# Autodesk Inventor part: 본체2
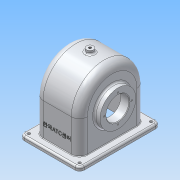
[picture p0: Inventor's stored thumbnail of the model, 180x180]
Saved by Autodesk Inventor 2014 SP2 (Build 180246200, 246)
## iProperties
Created: 2016-01
Part Number: 본체2
Material: 알루미늄 6061
Document SubType Name: Modeling
Designer: User
Mass: 842.835 g
Surface Area: 990.698 cm^2
Volume: 311.009 cm^3
Density: 2.71 g/cm^3
Appearance: 알루미늄 - 평지
Author: User
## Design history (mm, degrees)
sketch "스케치1"
  geometry: L1 (-57, 0)-(57, 0); L2 (57, 0)-(57, -64); L3 (57, -64)-(-57, -64); L4 (-57, -64)-(-57, 0); C1 r 57 at (0, 0); 2 further points
  constraints: 8 end point, 2 coincident, 2 parallel, 1 centre point, 1 horizontal, 1 midpoint, 1 perpendicular
  dimensions: "d0" = 114 diameter of C1; "d1" = 114 distance of L2.end L3.end; "d2" = 64 distance of L1.end L2.end
extrude "돌출1" new body sketch "스케치1" stored distance "d3" = 77; taper "d4" = 0 deg
feature "쉘1" dims "d7" = 6
sketch "스케치3"
  geometry: L1 (114, 0)-(114, -77) reference; L2 (0, 0)-(114, 0) reference; L3 (0, 0)-(0, -77) reference; L4 (114, -77)-(0, -77) reference; L5 (-13, 13.5)-(127, 13.5); L6 (127, 13.5)-(127, -90.5); L7 (127, -90.5)-(-13, -90.5); L8 (-13, -90.5)-(-13, 13.5); 3 further points
  constraints: 8 end point, 2 midpoint, 2 parallel, 1 horizontal, 1 horizontal alignment, 1 perpendicular, 1 vertical alignment
  dimensions: "d8" = 140 distance of L5.start L5.end; "d9" = 104 distance of L5.end L6.end
extrude "돌출2" join sketch "스케치3" distance "d10" = 7; taper "d11" = 0 deg
fillet "모깎기1" dims "d12" = 14
node "작업 평면1"
sketch "스케치6"
  geometry: C1 r 6 at (0, 0); 1 further point
  constraints: 1 centre point, 1 coincident
  dimensions: "d36" = 12 diameter of C1
extrude "돌출4" join sketch "스케치6" stored distance "d37" = 10; taper "d38" = 0 deg
hole "구멍2" diameter "d41" = 4.459; stored, may be unused: countersink angle "d45" = 90 deg, drill point angle "d47" = 118 deg; dims "d39" = 10, "d40" = 10, "d42" = 6, "d43" = 4, "d44" = 2, "d46" = 63
fillet "모깎기4" dims "d77" = 8
sketch "스케치9"
  geometry: A1 r 8 centre (119, 82.5) between (127, 82.5) and (119, 90.5) reference; A2 r 8 centre (-5, 82.5) between (-5, 90.5) and (-13, 82.5) reference; A3 r 8 centre (-5, -5.5) between (-13, -5.5) and (-5, -13.5) reference; A4 r 8 centre (119, -5.5) between (119, -13.5) and (127, -5.5) reference; 1 further point
hole "구멍5" sketch "스케치9" at (119, 82.5), (-5, 82.5), (119, -5.5), (-5, -5.5) diameter "d78" = 5; stored, may be unused: countersink angle "d82" = 90 deg, drill point angle "d84" = 118 deg; dims "d79" = 7, "d80" = 4, "d81" = 2, "d83" = 9
fillet "모깎기5" dims "d85" = 3
sketch "스케치10"
  geometry: L1 (49, 0)-(49, -57) reference; L2 (0, 0)-(49, 0) reference; L3 (0, -57)-(0, 0) reference; L4 (-1.387, -30.398)-(50.387, -30.398); L5 (50.387, -30.398)-(50.387, -37.602); L6 (50.387, -37.602)-(-1.387, -37.602); L7 (-1.387, -37.602)-(-1.387, -30.398); L8 (0, -34)-(49, -34); L9 (-19.5, -64)-(68.5, -64) reference; L10 (24.5, 0)-(24.5, -54); L11 (-14, 0)-(-14, -57) reference; L12 (68.5, -57)-(-19.5, -57) reference; 4 further points
  constraints: 4 end point, 4 midpoint, 2 point on line, 1 horizontal alignment, 1 perpendicular, 1 vertical alignment, 2 other
  dimensions: "d86" = 30 distance between parallel lines of L9 L8; "d87" = 38.5 distance between parallel lines of L11 L10
feature "엠보싱1" sketch "스케치10" dims "d8" = 140, "d9" = 104, "d88" = 0.5, "d89" = 0
sketch "스케치11"
  geometry: L1 (-51, -64)-(-51, 0) reference; L2 (51, -64)-(-51, -64) reference; L3 (51, 0)-(51, -64) reference; C1 r 20 at (0, -4) reference; A1 r 51 centre (0, 0) between (51, 0) and (-51, 0) reference
extrude "돌출5" cut sketch "스케치11" distance "d90" = 1; taper "d91" = 0 deg
sketch "스케치12"
  geometry: L1 (-51, -64)-(-51, 0) reference; L2 (51, -64)-(-51, -64) reference; L3 (51, 0)-(51, -64) reference; C1 r 38.908 at (0, -4) reference; A1 r 51 centre (0, 0) between (51, 0) and (-51, 0) reference
extrude "돌출6" cut sketch "스케치12" distance "d92" = 1; taper "d93" = 0 deg
sketch "스케치13"
  geometry: L1 (-4, 43.197)-(-4, -48.942); L2 (-64, -33.5)-(-64, 33.5) reference; L3 (16, 35.5)-(30.899, 35.5); L4 (24, 35.5)-(24, 19.5); L5 (24, 19.5)-(16, 19.5); L6 (16, 19.5)-(16, 35.5); L7 (0, 38.5)-(43, 38.5) reference; L8 (24, 19.5)-(39.943, 38.5); L9 (30.899, 35.5)-(33.416, 38.5); L10 (-4, 33.5)-(16, 33.5); L11 (-4, 38.5)-(33.416, 38.5); L12 (-4, 38.5)-(-4, 33.5); 1 further point
  constraints: 20 end point, 6 point on line, 3 parallel, 2 perpendicular, 1 collinear, 1 horizontal, 1 vertical
  dimensions: "d95" = 60 distance between parallel lines of L1 L2; "d96" = 20 distance between parallel lines of L1 L6; "d99" = 50 deg angle of L8 L5; "d100" = 5 distance between parallel lines of L8 L9; "d102" = 5 distance between parallel lines of L10 L11; "d103" = 56 diameter of L4 L1; "d104" = 19 distance between parallel lines of L11 L5; "d105" = 3 distance between parallel lines of L11 L3
revolve "회전3" stored, may be unused: angle "d106" = 90 deg
revolve "회전4" stored, may be unused: angle "d107" = 90 deg
sketch "스케치14"
  geometry: C1 r 20 at (0, -4) reference; C2 r 31 at (0, -4)
  constraints: 1 centre point, 1 coincident
  dimensions: "d108" = 62 diameter of C2
extrude "돌출7" join sketch "스케치14" distance "d109" = 10; taper "d110" = 0 deg
hole "구멍6" diameter "d113" = 40; stored, may be unused: countersink angle "d117" = 90 deg, drill point angle "d119" = 118 deg; dims "d111" = 10, "d112" = 10, "d114" = 6, "d115" = 4, "d116" = 2, "d118" = 8
chamfer "모따기3" distance "d120" = 1; stored, may be unused: second distance "d121" = 2, angle "d122" = 45 deg
fillet "모깎기6" dims "d123" = 3
sketch "스케치15"
  geometry: C1 r 31 at (0, 0) reference; 2 further points
  constraints: 1 vertical alignment
  dimensions: "d124" = 24 distance of C1.centre point (0, 24)
hole "구멍7" sketch "스케치15" at (0, 24) diameter "d125" = 2.459; stored, may be unused: countersink angle "d129" = 90 deg, drill point angle "d131" = 118 deg; dims "d126" = 6, "d127" = 4, "d128" = 2, "d130" = 8
sketch "스케치16"
  geometry: C1 r 21 at (0, 0) reference; 2 further points
  constraints: 1 vertical alignment
  dimensions: "d135" = 28 distance of C1.centre point (0, 28)
hole "구멍8" sketch "스케치16" at (0, 28) diameter "d136" = 2.459; stored, may be unused: countersink angle "d140" = 90 deg, drill point angle "d142" = 118 deg; dims "d137" = 7, "d138" = 4, "d139" = 2, "d141" = 9
fillet "모깎기7" dims "d146" = 6
fillet "모깎기8" dims "d147" = 3
fillet "모깎기9" dims "d148" = 1
node "솔리드1"
pattern_circular "원형 패턴3" dims angle "d133" = 360 deg
pattern_circular "원형 패턴4" dims angle "d144" = 360 deg
other parameters: "d35" = 63
